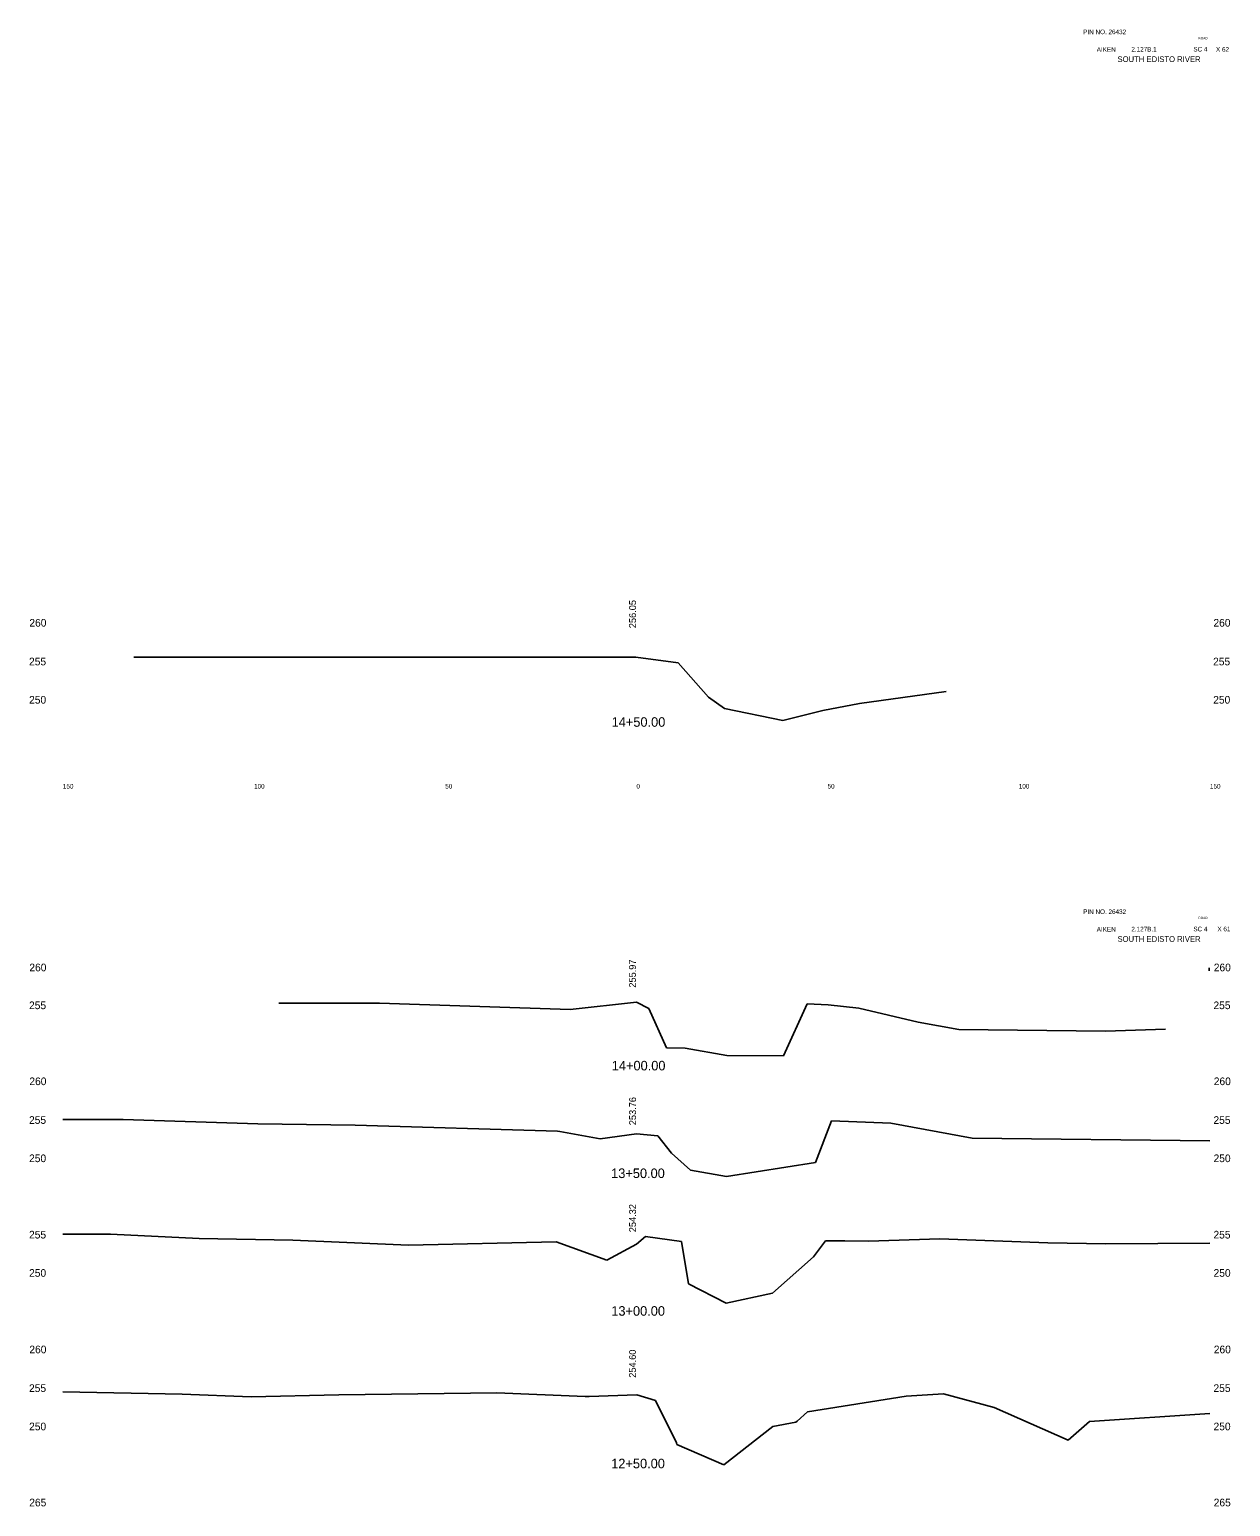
# Model space of a CAD drawing. Extents: x 557 to 872, y 628 to 2216.
# Drawn here: x 557.8 to 871.9, y 1830 to 2216.3 of the extents above; entities that cross this region are included whole.
import ezdxf

# ---------------------------------------------------------------- set-up
doc = ezdxf.new("R2010")
doc.units = 0
for name, color, linetype in [('Level 1', 7, 'Continuous'), ('Level 10', 7, 'Continuous'), ('Level 13', 7, 'Continuous'), ('Level 2', 7, 'Continuous'), ('Level 3', 7, 'Continuous'), ('Level 60', 7, 'Continuous')]:
    doc.layers.add(name, color=color, linetype=linetype)

msp = doc.modelspace()

# ---------------------------------------------------------------- linework, layer by layer
at = {"layer": 'Level 2'}
msp.add_line((866.32, 1970.09), (866.32, 1970.89), dxfattribs=at)
at = {"layer": 'Level 60'}
for p, q in [((716.38, 2052.12), (585.06, 2052.12)), ((716.38, 2052.12), (727.46, 2050.7)), ((727.46, 2050.7), (735.36, 2041.74)), ((735.36, 2041.74), (739.61, 2038.74)), ((765.31, 2038.24), (774.91, 2040.07)), ((774.91, 2040.07), (797.54, 2043.14)), ((739.61, 2038.74), (754.81, 2035.64)), ((754.81, 2035.64), (765.31, 2038.24)), ((623.01, 1961.71), (649.37, 1961.7)), ((649.37, 1961.7), (699.24, 1960.04)), ((699.24, 1960.04), (716.54, 1961.94)), ((716.54, 1961.94), (719.8, 1960.29)), ((719.8, 1960.29), (724.38, 1950.01)), ((754.97, 1947.86), (761.22, 1961.47)), ((761.22, 1961.47), (766.68, 1961.24)), ((766.68, 1961.24), (774.74, 1960.4)), ((774.74, 1960.4), (790.23, 1956.73)), ((790.23, 1956.73), (800.88, 1954.78)), ((800.88, 1954.78), (839.25, 1954.31)), ((839.25, 1954.31), (854.95, 1954.84)), ((724.38, 1950.01), (729.27, 1949.93)), ((729.27, 1949.93), (740.18, 1947.98)), ((740.18, 1947.98), (754.97, 1947.86)), ((566.54, 1931.28), (582.31, 1931.27)), ((582.31, 1931.27), (617.55, 1930.11)), ((617.55, 1930.11), (643.02, 1929.78)), ((643.02, 1929.78), (695.87, 1928.16)), ((695.87, 1928.16), (696.48, 1928.13)), ((696.48, 1928.13), (707.1, 1926.23)), ((707.1, 1926.23), (716.54, 1927.51)), ((716.54, 1927.51), (722.1, 1926.97)), ((763.38, 1920), (767.59, 1930.89)), ((767.59, 1930.89), (783.08, 1930.32)), ((783.08, 1930.32), (804.35, 1926.41)), ((722.1, 1926.97), (725.72, 1922.42)), ((804.35, 1926.41), (866.54, 1925.65)), ((725.72, 1922.42), (730.69, 1918.04)), ((740.12, 1916.36), (763.38, 1920)), ((730.69, 1918.04), (740.12, 1916.36)), ((566.54, 1901.27), (579.03, 1901.22)), ((579.03, 1901.22), (602.16, 1900.12)), ((716.54, 1898.64), (718.89, 1900.67)), ((718.89, 1900.67), (728.3, 1899.37)), ((602.16, 1900.12), (626.72, 1899.67)), ((626.72, 1899.67), (656.94, 1898.41)), ((656.94, 1898.41), (695.59, 1899.24)), ((695.59, 1899.24), (708.79, 1894.45)), ((708.79, 1894.45), (716.54, 1898.64)), ((728.3, 1899.37), (730.2, 1888.27)), ((762.81, 1895.33), (766, 1899.56)), ((766, 1899.56), (771.02, 1899.5)), ((771.02, 1899.5), (777.2, 1899.42)), ((777.2, 1899.42), (795.88, 1900.01)), ((795.88, 1900.01), (824.11, 1899.03)), ((824.11, 1899.03), (839.33, 1898.75)), ((839.33, 1898.75), (866.54, 1898.91)), ((752.14, 1885.85), (762.81, 1895.33)), ((730.2, 1888.27), (740.04, 1883.18)), ((740.04, 1883.18), (752.14, 1885.85)), ((566.54, 1860.03), (597.77, 1859.45)), ((597.77, 1859.45), (615.75, 1858.71)), ((615.75, 1858.71), (638.69, 1859.2)), ((638.69, 1859.2), (680.06, 1859.79)), ((680.06, 1859.79), (703.15, 1858.79)), ((703.15, 1858.79), (704.21, 1858.8)), ((704.21, 1858.8), (716.68, 1859.2)), ((716.68, 1859.2), (721.53, 1857.72)), ((761.25, 1854.81), (787.09, 1858.86)), ((787.09, 1858.86), (796.89, 1859.5)), ((796.89, 1859.5), (810.14, 1855.91)), ((721.53, 1857.72), (727.02, 1846.67)), ((758.62, 1852.37), (761.25, 1854.81)), ((810.14, 1855.91), (829.49, 1847.4)), ((835.07, 1852.31), (866.54, 1854.32)), ((739.4, 1840.91), (752.2, 1850.99)), ((752.2, 1850.99), (758.24, 1852.09)), ((758.24, 1852.09), (758.62, 1852.37)), ((829.49, 1847.4), (835.07, 1852.31)), ((727.02, 1846.67), (727.07, 1846.26)), ((727.07, 1846.26), (739.4, 1840.91))]:
    msp.add_line(p, q, dxfattribs=at)

# ---------------------------------------------------------------- texts
at = {"layer": 'Level 1'}
for s, height, p in [('PIN NO. 26432', 1.2, (833.38, 2215.09)), ('ROAD', 0.6, (863.53, 2213.75)), ('AIKEN', 1.2, (836.93, 2210.49)), (' 2.127B.1', 1.2, (845.53, 2210.54)), ('SC 4', 1.2, (862.2, 2210.56)), ('X 62', 1.2, (868.12, 2210.51)), ('SOUTH EDISTO RIVER', 1.5, (842.36, 2207.8)), ('14+50.00', 2.5, (710.06, 2033.96)), ('PIN NO. 26432', 1.2, (833.38, 1985)), ('AIKEN', 1.2, (836.93, 1980.4)), (' 2.127B.1', 1.2, (845.53, 1980.45)), ('SC 4', 1.2, (862.2, 1980.47)), ('ROAD', 0.6, (863.53, 1983.67)), ('X 61', 1.2, (868.49, 1980.48)), ('SOUTH EDISTO RIVER', 1.5, (842.36, 1977.71)), ('14+00.00', 2.5, (710.1, 1944.09)), ('13+50.00', 2.5, (709.93, 1915.94)), ('13+00.00', 2.5, (709.97, 1879.93)), ('12+50.00', 2.5, (709.95, 1840.03))]:
    msp.add_text(s, height=height, dxfattribs=at).set_placement(p)
at = {"layer": 'Level 10'}
for s, p in [('256.05', (716.43, 2059.74)), ('255.97', (716.41, 1965.73)), ('253.76', (716.44, 1929.76)), ('254.32', (716.43, 1901.77)), ('254.60', (716.42, 1863.71))]:
    msp.add_text(s, height=1.8, rotation=90, dxfattribs=at).set_placement(p)
at = {"layer": 'Level 13'}
for s, p in [('150', (566.54, 2017.8)), ('100', (616.54, 2017.8)), ('50', (666.54, 2017.8)), ('0', (716.54, 2017.8)), ('50', (766.54, 2017.8)), ('100', (816.54, 2017.8)), ('150', (866.54, 2017.8))]:
    msp.add_text(s, height=1.2, dxfattribs=at).set_placement(p)
at = {"layer": 'Level 3'}
for s, p in [(' 260', (557.03, 2060.15)), (' 260', (866.71, 2060.15)), (' 255', (556.94, 2050.02)), (' 255', (866.62, 2050.02)), (' 250', (556.96, 2040.01)), (' 250', (866.65, 2040.01)), (' 260', (557.03, 1970.01)), (' 260', (866.8, 1970.01)), (' 255', (556.94, 1960.11)), (' 255', (866.72, 1960.11)), (' 260', (557.03, 1940.24)), (' 260', (866.8, 1940.24)), (' 255', (556.94, 1930.11)), (' 255', (866.72, 1930.11)), (' 250', (556.96, 1920.1)), (' 250', (866.74, 1920.1)), (' 255', (556.94, 1900.13)), (' 255', (866.72, 1900.13)), (' 250', (556.96, 1890.12)), (' 250', (866.74, 1890.12)), (' 260', (557.03, 1870.11)), (' 260', (866.8, 1870.11)), (' 255', (556.94, 1859.99)), (' 255', (866.72, 1859.99)), (' 250', (556.96, 1849.97)), (' 250', (866.74, 1849.97)), (' 265', (557, 1830.08)), (' 265', (866.78, 1830.08))]:
    msp.add_text(s, height=2, dxfattribs=at).set_placement(p)

doc.saveas('drawing.dxf')
